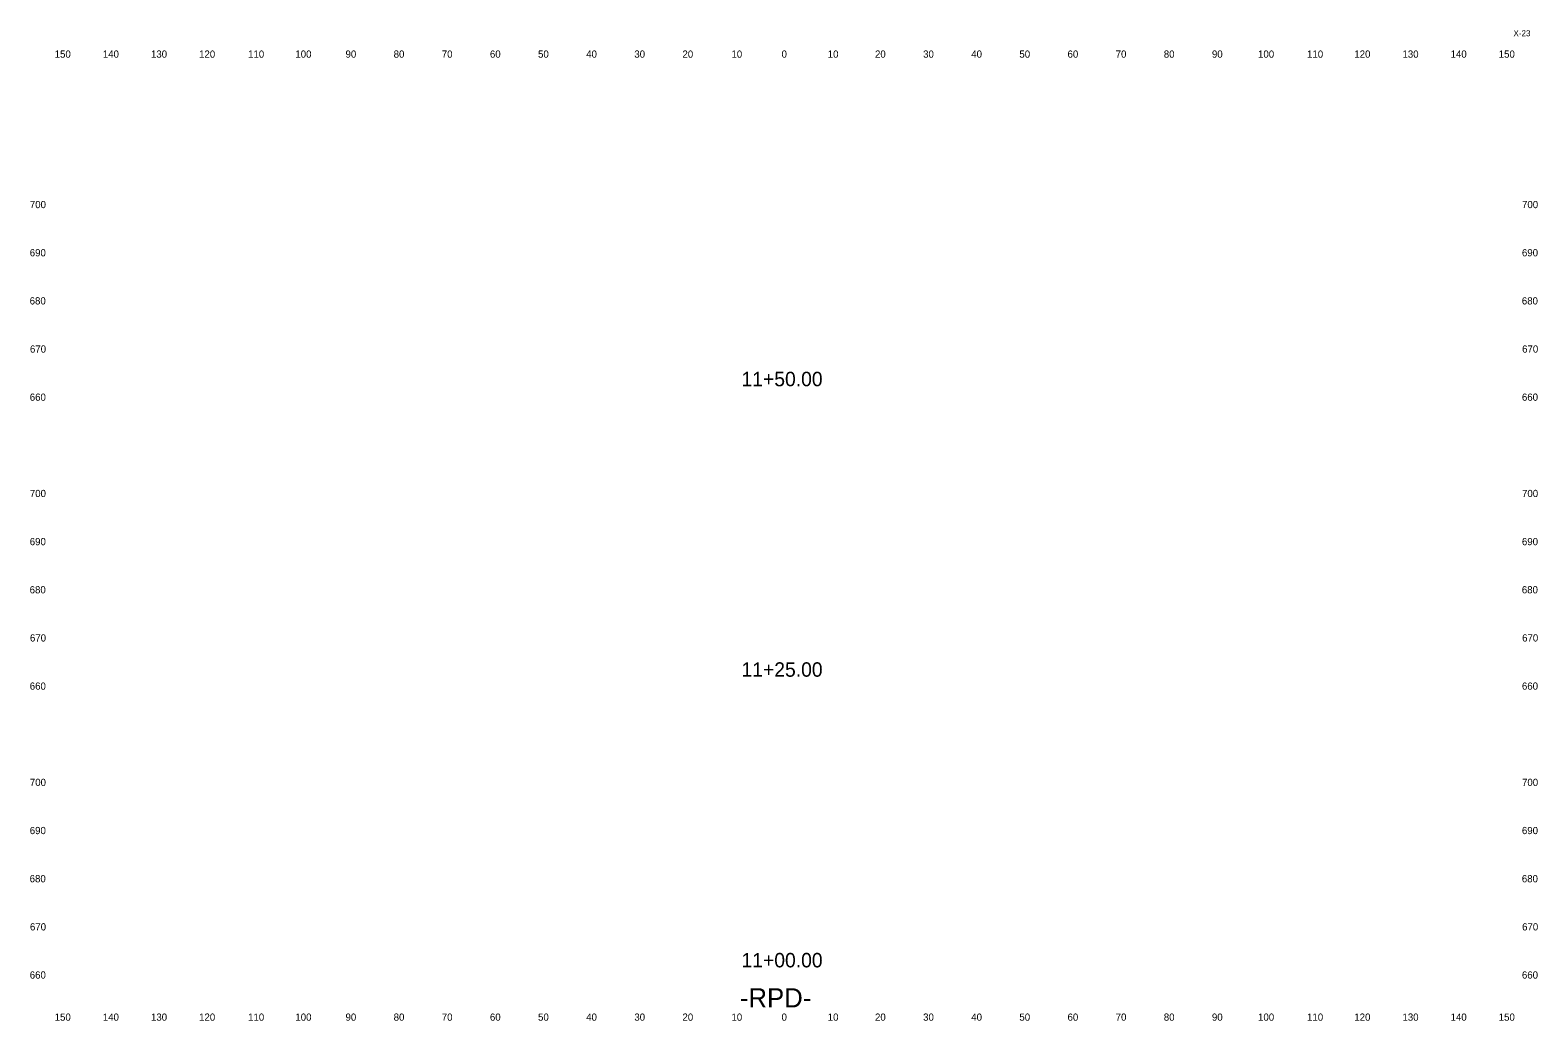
# Model space of a CAD drawing. Extents: x 3 to 317, y 1 to 867.
# Drawn here: x 3.3 to 316.6, y 1.2 to 207 of the extents above; entities that cross this region are included whole.
import ezdxf

# ---------------------------------------------------------------- set-up
doc = ezdxf.new("R2010")
doc.units = 0
for name, color, linetype in [('Prop XS Alignment Label', 7, 'Continuous'), ('Prop XS Elevation Labels', 7, 'Continuous'), ('Prop XS Offset Labels', 7, 'Continuous'), ('Prop XS Sheet Number', 7, 'Continuous'), ('Prop XS Station Labels', 7, 'Continuous')]:
    doc.layers.add(name, color=color, linetype=linetype)

msp = doc.modelspace()

# ---------------------------------------------------------------- texts
at = {"layer": 'Prop XS Alignment Label'}
msp.add_text('-RPD-', height=4, dxfattribs=at).set_placement((150.78, 4))
at = {"layer": 'Prop XS Elevation Labels'}
for s, p in [('700', (3.28, 170)), ('700', (313.28, 170)), ('690', (3.26, 160)), ('690', (313.26, 160)), ('680', (3.24, 150)), ('680', (313.24, 150)), ('670', (3.3, 140)), ('670', (313.3, 140)), ('660', (3.26, 130)), ('660', (313.26, 130)), ('700', (3.28, 110)), ('700', (313.28, 110)), ('690', (3.26, 100)), ('690', (313.26, 100)), ('680', (3.24, 90)), ('680', (313.24, 90)), ('670', (3.3, 80)), ('670', (313.3, 80)), ('660', (3.26, 70)), ('660', (313.26, 70)), ('700', (3.28, 50)), ('700', (313.28, 50)), ('690', (3.26, 40)), ('690', (313.26, 40)), ('680', (3.24, 30)), ('680', (313.24, 30)), ('670', (3.3, 20)), ('670', (313.3, 20)), ('660', (3.26, 10)), ('660', (313.26, 10))]:
    msp.add_text(s, height=1.5, dxfattribs=at).set_placement(p)
at = {"layer": 'Prop XS Offset Labels'}
for s, p in [('150', (8.44, 201.25)), ('140', (18.44, 201.25)), ('130', (28.44, 201.25)), ('120', (38.44, 201.25)), ('110', (48.62, 201.25)), ('100', (58.44, 201.25)), ('90', (68.86, 201.25)), ('80', (78.86, 201.25)), ('70', (88.86, 201.25)), ('60', (98.86, 201.25)), ('50', (108.86, 201.25)), ('40', (118.86, 201.25)), ('30', (128.86, 201.25)), ('20', (138.86, 201.25)), ('10', (149.04, 201.25)), ('0', (159.45, 201.25)), ('10', (169.04, 201.25)), ('20', (178.86, 201.25)), ('30', (188.86, 201.25)), ('40', (198.86, 201.25)), ('50', (208.86, 201.25)), ('60', (218.86, 201.25)), ('70', (228.86, 201.25)), ('80', (238.86, 201.25)), ('90', (248.86, 201.25)), ('100', (258.44, 201.25)), ('110', (268.62, 201.25)), ('120', (278.44, 201.25)), ('130', (288.44, 201.25)), ('140', (298.44, 201.25)), ('150', (308.44, 201.25)), ('150', (8.44, 1.25)), ('140', (18.44, 1.25)), ('130', (28.44, 1.25)), ('120', (38.44, 1.25)), ('110', (48.62, 1.25)), ('100', (58.44, 1.25)), ('90', (68.86, 1.25)), ('80', (78.86, 1.25)), ('70', (88.86, 1.25)), ('60', (98.86, 1.25)), ('50', (108.86, 1.25)), ('40', (118.86, 1.25)), ('30', (128.86, 1.25)), ('20', (138.86, 1.25)), ('10', (149.04, 1.25)), ('0', (159.45, 1.25)), ('10', (169.04, 1.25)), ('20', (178.86, 1.25)), ('30', (188.86, 1.25)), ('40', (198.86, 1.25)), ('50', (208.86, 1.25)), ('60', (218.86, 1.25)), ('70', (228.86, 1.25)), ('80', (238.86, 1.25)), ('90', (248.86, 1.25)), ('100', (258.44, 1.25)), ('110', (268.62, 1.25)), ('120', (278.44, 1.25)), ('130', (288.44, 1.25)), ('140', (298.44, 1.25)), ('150', (308.44, 1.25))]:
    msp.add_text(s, height=1.5, dxfattribs=at).set_placement(p)
at = {"layer": 'Prop XS Sheet Number'}
msp.add_text('X-23', height=1.25, dxfattribs=at).set_placement((311.5, 205.7))
at = {"layer": 'Prop XS Station Labels'}
for s, p in [('11+50.00', (151.13, 133.02)), ('11+25.00', (151.13, 72.69)), ('11+00.00', (151.13, 12.33))]:
    msp.add_text(s, height=3, dxfattribs=at).set_placement(p)

doc.saveas('drawing.dxf')
